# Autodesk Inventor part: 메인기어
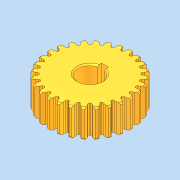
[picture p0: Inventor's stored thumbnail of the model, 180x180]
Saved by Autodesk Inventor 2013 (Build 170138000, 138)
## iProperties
Company: 한국ATC센터
Created: 2014-12
Part Number: 메인기어
Document SubType Name: Modeling
Designer: KYOUNG IL JANG
Density: 1 g/cm^3
Mass: 43.883 g
Surface Area: 122.661 cm^2
Volume: 43.883 cm^3
Material: 일반
Author: KYOUNG IL JANG
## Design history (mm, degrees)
sketch "스케치1"
  geometry: C1 r 25.5 at (0, 0); A1 r 1.064 centre (-2.94, 26.392) between (-2.696, 25.357) and (-1.877, 26.361); A2 r 6.991 centre (5.094, 25.835) between (-1.626, 27.763) and (-1.877, 26.361); A3 r 11.864 centre (9.774, 24.478) between (-0.731, 29.991) and (-1.626, 27.763); A4 r 1.064 centre (2.94, 26.392) between (1.877, 26.361) and (2.696, 25.357); A5 r 6.991 centre (-5.094, 25.835) between (1.877, 26.361) and (1.626, 27.763); A6 r 11.864 centre (-9.774, 24.478) between (1.626, 27.763) and (0.731, 29.991); A7 r 25.5 centre (0, 0) between (2.696, 25.357) and (-2.696, 25.357); A8 r 30 centre (0, 0) between (0.731, 29.991) and (-0.731, 29.991); 1 further point
  constraints: 16 point on circle, 9 centre point, 2 coincident, 1 concentric
extrude "돌출1" new body sketch "스케치1" stored distance "d0" = 20; taper "d1" = 0 deg
extrude "돌출2" join sketch "스케치1" stored distance "d2" = 20; taper "d3" = 0 deg
chamfer "모따기1" distance "d4" = 1; stored, may be unused: second distance "d5" = 2, angle "d6" = 45 deg
hole "구멍1" diameter "d12" = 17; stored, may be unused: countersink angle "d16" = 90 deg, drill point angle "d18" = 118 deg; dims "d10" = 10, "d11" = 10, "d13" = 6, "d14" = 4, "d15" = 2, "d17" = 8
sketch "스케치2"
  geometry: L1 (-2.5, 8.124)-(-2.5, 10.8); L2 (-2.5, 10.8)-(2.5, 10.8); L3 (2.5, 10.8)-(2.5, 8.124); A1 r 8.5 centre (0, 0) between (-2.5, 8.124) and (2.5, 8.124) reference; 1 further point
  constraints: 6 end point, 2 parallel, 2 point on circle, 1 perpendicular, 1 vertical
  dimensions: "d19" = 5 distance of L1.end L2.end; "d20" = 2.3 distance edge to line of A1 L2
extrude "돌출3" cut sketch "스케치2" stored distance "d21" = 20; taper "d22" = 0 deg
chamfer "모따기2" distance "d23" = 1; stored, may be unused: second distance "d24" = 2, angle "d25" = 45 deg
node "솔리드1"
pattern_circular "원형 패턴1" dims angle "d8" = 360 deg
